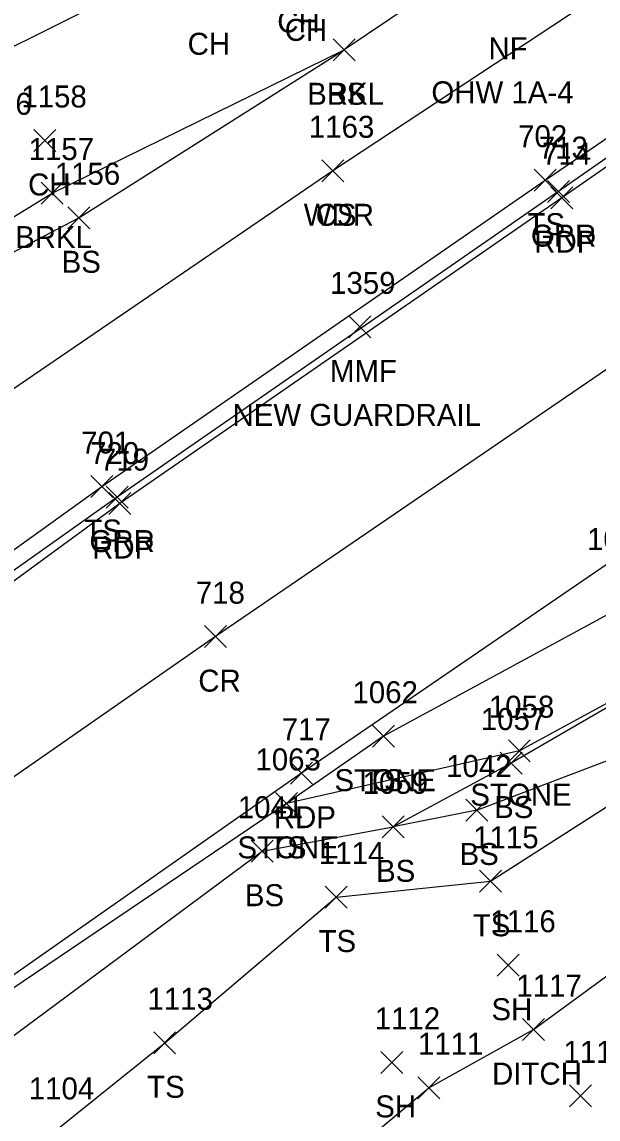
# Model space of a CAD drawing. Extents: x 1528286 to 1556263, y 492387 to 508952.
# Drawn here: x 1528810.2 to 1528862.6, y 492861.6 to 492961.3 of the extents above; entities that cross this region are included whole.
import ezdxf

# ---------------------------------------------------------------- set-up
doc = ezdxf.new("R2010")
doc.units = 0
for name, color, linetype in [('D_A', 7, 'Continuous'), ('D_I', 7, 'Continuous'), ('D_TIC', 7, 'Continuous'), ('DD', 7, 'Continuous'), ('L_A', 7, 'Continuous'), ('L_C', 7, 'Continuous'), ('L_I', 7, 'Continuous'), ('L_TIC', 7, 'Continuous'), ('LASF', 7, 'Continuous'), ('LAWA', 7, 'Continuous'), ('LAWE', 7, 'Continuous'), ('LELB', 7, 'Continuous'), ('P_A', 7, 'Continuous'), ('P_I', 7, 'Continuous'), ('P_TIC', 7, 'Continuous'), ('PET', 7, 'Continuous'), ('PRC', 7, 'Continuous'), ('R_A', 7, 'Continuous'), ('R_I', 7, 'Continuous'), ('R_TIC', 7, 'Continuous'), ('RGR', 7, 'Continuous')]:
    doc.layers.add(name, color=color, linetype=linetype)

msp = doc.modelspace()

# ---------------------------------------------------------------- linework, layer by layer
at = {"layer": 'D_TIC'}
for points in [[(1528855.697, 492868.705), (1528857.697, 492870.705)], [(1528857.697, 492868.705), (1528855.697, 492870.705)], [(1528855.697, 492868.705), (1528857.697, 492870.705)], [(1528857.697, 492868.705), (1528855.697, 492870.705)], [(1528846.183, 492863.422), (1528848.183, 492865.422)], [(1528848.183, 492863.422), (1528846.183, 492865.422)], [(1528846.183, 492863.422), (1528848.183, 492865.422)], [(1528848.183, 492863.422), (1528846.183, 492865.422)]]:
    msp.add_lwpolyline(points, dxfattribs=at)
at = {"layer": 'DD'}
msp.add_lwpolyline([(1528821.309, 492845.775), (1528834.865, 492854.142), (1528847.183, 492864.422), (1528856.697, 492869.705), (1528876.113, 492883.9), (1528885.264, 492891.293)], dxfattribs=at)
msp.add_lwpolyline([(1528821.309, 492845.775), (1528834.865, 492854.142), (1528847.183, 492864.422), (1528856.697, 492869.705), (1528876.113, 492883.9), (1528885.264, 492891.293)], dxfattribs=at)
at = {"layer": 'L_TIC'}
for points in [[(1528838.473, 492957.791), (1528840.473, 492959.791)], [(1528840.473, 492957.791), (1528838.473, 492959.791)], [(1528838.473, 492957.791), (1528840.473, 492959.791)], [(1528840.473, 492957.791), (1528838.473, 492959.791)], [(1528838.473, 492957.791), (1528840.473, 492959.791)], [(1528840.473, 492957.791), (1528838.473, 492959.791)], [(1528838.473, 492957.791), (1528840.473, 492959.791)], [(1528840.473, 492957.791), (1528838.473, 492959.791)], [(1528811.255, 492949.545), (1528813.255, 492951.545)], [(1528813.255, 492949.545), (1528811.255, 492951.545)], [(1528811.255, 492949.545), (1528813.255, 492951.545)], [(1528813.255, 492949.545), (1528811.255, 492951.545)], [(1528837.449, 492946.788), (1528839.449, 492948.788)], [(1528839.449, 492946.788), (1528837.449, 492948.788)], [(1528837.449, 492946.788), (1528839.449, 492948.788)], [(1528839.449, 492946.788), (1528837.449, 492948.788)], [(1528837.449, 492946.788), (1528839.449, 492948.788)], [(1528839.449, 492946.788), (1528837.449, 492948.788)], [(1528837.449, 492946.788), (1528839.449, 492948.788)], [(1528839.449, 492946.788), (1528837.449, 492948.788)], [(1528856.746, 492945.937), (1528858.746, 492947.937)], [(1528858.746, 492945.937), (1528856.746, 492947.937)], [(1528856.746, 492945.937), (1528858.746, 492947.937)], [(1528858.746, 492945.937), (1528856.746, 492947.937)], [(1528811.92, 492944.763), (1528813.92, 492946.763)], [(1528813.92, 492944.763), (1528811.92, 492946.763)], [(1528811.92, 492944.763), (1528813.92, 492946.763)], [(1528813.92, 492944.763), (1528811.92, 492946.763)], [(1528814.352, 492942.517), (1528816.352, 492944.517)], [(1528816.352, 492942.517), (1528814.352, 492944.517)], [(1528814.352, 492942.517), (1528816.352, 492944.517)], [(1528816.352, 492942.517), (1528814.352, 492944.517)], [(1528839.906, 492932.599), (1528841.906, 492934.599)], [(1528841.906, 492932.599), (1528839.906, 492934.599)], [(1528839.906, 492932.599), (1528841.906, 492934.599)], [(1528841.906, 492932.599), (1528839.906, 492934.599)], [(1528816.445, 492918.082), (1528818.445, 492920.082)], [(1528818.445, 492918.082), (1528816.445, 492920.082)], [(1528816.445, 492918.082), (1528818.445, 492920.082)], [(1528818.445, 492918.082), (1528816.445, 492920.082)], [(1528842.058, 492895.384), (1528844.058, 492897.384)], [(1528844.058, 492895.384), (1528842.058, 492897.384)], [(1528842.058, 492895.384), (1528844.058, 492897.384)], [(1528844.058, 492895.384), (1528842.058, 492897.384)], [(1528842.058, 492895.384), (1528844.058, 492897.384)], [(1528844.058, 492895.384), (1528842.058, 492897.384)], [(1528842.058, 492895.384), (1528844.058, 492897.384)], [(1528844.058, 492895.384), (1528842.058, 492897.384)], [(1528854.412, 492894.062), (1528856.412, 492896.062)], [(1528856.412, 492894.062), (1528854.412, 492896.062)], [(1528854.412, 492894.062), (1528856.412, 492896.062)], [(1528856.412, 492894.062), (1528854.412, 492896.062)], [(1528853.678, 492892.942), (1528855.678, 492894.942)], [(1528855.678, 492892.942), (1528853.678, 492894.942)], [(1528853.678, 492892.942), (1528855.678, 492894.942)], [(1528855.678, 492892.942), (1528853.678, 492894.942)], [(1528833.233, 492889.275), (1528835.233, 492891.275)], [(1528835.233, 492889.275), (1528833.233, 492891.275)], [(1528833.233, 492889.275), (1528835.233, 492891.275)], [(1528835.233, 492889.275), (1528833.233, 492891.275)], [(1528833.233, 492889.275), (1528835.233, 492891.275)], [(1528835.233, 492889.275), (1528833.233, 492891.275)], [(1528833.233, 492889.275), (1528835.233, 492891.275)], [(1528835.233, 492889.275), (1528833.233, 492891.275)], [(1528833.233, 492889.275), (1528835.233, 492891.275)], [(1528835.233, 492889.275), (1528833.233, 492891.275)], [(1528833.233, 492889.275), (1528835.233, 492891.275)], [(1528835.233, 492889.275), (1528833.233, 492891.275)], [(1528850.535, 492888.673), (1528852.535, 492890.673)], [(1528852.535, 492888.673), (1528850.535, 492890.673)], [(1528850.535, 492888.673), (1528852.535, 492890.673)], [(1528852.535, 492888.673), (1528850.535, 492890.673)], [(1528842.943, 492887.142), (1528844.943, 492889.142)], [(1528844.943, 492887.142), (1528842.943, 492889.142)], [(1528842.943, 492887.142), (1528844.943, 492889.142)], [(1528844.943, 492887.142), (1528842.943, 492889.142)], [(1528831.015, 492884.927), (1528833.015, 492886.927)], [(1528833.015, 492884.927), (1528831.015, 492886.927)], [(1528831.015, 492884.927), (1528833.015, 492886.927)], [(1528833.015, 492884.927), (1528831.015, 492886.927)], [(1528851.776, 492882.19), (1528853.776, 492884.19)], [(1528853.776, 492882.19), (1528851.776, 492884.19)], [(1528851.776, 492882.19), (1528853.776, 492884.19)], [(1528853.776, 492882.19), (1528851.776, 492884.19)], [(1528837.745, 492880.757), (1528839.745, 492882.757)], [(1528839.745, 492880.757), (1528837.745, 492882.757)], [(1528837.745, 492880.757), (1528839.745, 492882.757)], [(1528839.745, 492880.757), (1528837.745, 492882.757)], [(1528853.388, 492874.56), (1528855.388, 492876.56)], [(1528855.388, 492874.56), (1528853.388, 492876.56)], [(1528853.388, 492874.56), (1528855.388, 492876.56)], [(1528855.388, 492874.56), (1528853.388, 492876.56)], [(1528822.162, 492867.505), (1528824.162, 492869.505)], [(1528824.162, 492867.505), (1528822.162, 492869.505)], [(1528822.162, 492867.505), (1528824.162, 492869.505)], [(1528824.162, 492867.505), (1528822.162, 492869.505)], [(1528842.818, 492865.724), (1528844.818, 492867.724)], [(1528844.818, 492865.724), (1528842.818, 492867.724)], [(1528842.818, 492865.724), (1528844.818, 492867.724)], [(1528844.818, 492865.724), (1528842.818, 492867.724)], [(1528859.987, 492862.683), (1528861.987, 492864.683)], [(1528861.987, 492862.683), (1528859.987, 492864.683)], [(1528859.987, 492862.683), (1528861.987, 492864.683)], [(1528861.987, 492862.683), (1528859.987, 492864.683)]]:
    msp.add_lwpolyline(points, dxfattribs=at)
at = {"layer": 'LASF'}
for points in [[(1528892.931, 492919.077), (1528869.957, 492910.976), (1528843.058, 492896.384), (1528834.233, 492890.275)], [(1528892.931, 492919.077), (1528869.957, 492910.976), (1528843.058, 492896.384), (1528834.233, 492890.275)], [(1528890.826, 492909.115), (1528874.507, 492905.431), (1528855.412, 492895.062), (1528834.233, 492890.275)], [(1528890.826, 492909.115), (1528874.507, 492905.431), (1528855.412, 492895.062), (1528834.233, 492890.275)]]:
    msp.add_lwpolyline(points, dxfattribs=at)
at = {"layer": 'LAWA'}
msp.add_lwpolyline([(1528932.821, 493004.859), (1528877.302, 492973.439), (1528838.449, 492947.788), (1528805.62, 492925.402), (1528761.436, 492893.561), (1528731.583, 492876.413)], dxfattribs=at)
msp.add_lwpolyline([(1528932.821, 493004.859), (1528877.302, 492973.439), (1528838.449, 492947.788), (1528805.62, 492925.402), (1528761.436, 492893.561), (1528731.583, 492876.413)], dxfattribs=at)
at = {"layer": 'LAWE'}
for points in [[(1528718.656, 492995.484), (1528788.188, 492988.485), (1528851.648, 492980.148), (1528805.688, 492957.255), (1528774.988, 492939.585), (1528746.812, 492927.03)], [(1528718.656, 492995.484), (1528788.188, 492988.485), (1528851.648, 492980.148), (1528805.688, 492957.255), (1528774.988, 492939.585), (1528746.812, 492927.03)], [(1528860.159, 492972.685), (1528839.473, 492958.791)], [(1528860.159, 492972.685), (1528839.473, 492958.791)], [(1528699.698, 492858.914), (1528705.195, 492868.423), (1528711.604, 492880.328), (1528733.006, 492898.336), (1528756.206, 492910.282), (1528789.072, 492931.124), (1528812.92, 492945.763), (1528839.473, 492958.791)], [(1528699.698, 492858.914), (1528705.195, 492868.423), (1528711.604, 492880.328), (1528733.006, 492898.336), (1528756.206, 492910.282), (1528789.072, 492931.124), (1528812.92, 492945.763), (1528839.473, 492958.791)]]:
    msp.add_lwpolyline(points, dxfattribs=at)
at = {"layer": 'LELB'}
for points in [[(1528932.821, 493004.859), (1528877.302, 492973.439), (1528838.449, 492947.788), (1528805.62, 492925.402)], [(1528932.821, 493004.859), (1528877.302, 492973.439), (1528838.449, 492947.788), (1528805.62, 492925.402)], [(1528511.531, 492702.846), (1528534.14, 492721.314), (1528572.642, 492751.164), (1528586.729, 492763.586), (1528600.497, 492766.346), (1528613.458, 492775.516), (1528652.2, 492802.526), (1528688.619, 492828.262), (1528710.289, 492843.118), (1528742.907, 492866.471), (1528778.713, 492891.266), (1528817.445, 492919.082), (1528857.746, 492946.937), (1528897.372, 492973.983), (1528940.286, 493003.739)], [(1528511.531, 492702.846), (1528534.14, 492721.314), (1528572.642, 492751.164), (1528586.729, 492763.586), (1528600.497, 492766.346), (1528613.458, 492775.516), (1528652.2, 492802.526), (1528688.619, 492828.262), (1528710.289, 492843.118), (1528742.907, 492866.471), (1528778.713, 492891.266), (1528817.445, 492919.082), (1528857.746, 492946.937), (1528897.372, 492973.983), (1528940.286, 493003.739)], [(1528716.329, 492882.991), (1528739.424, 492897.091), (1528757.723, 492908.665), (1528787.402, 492928.88), (1528815.352, 492943.517), (1528839.473, 492958.791)], [(1528716.329, 492882.991), (1528739.424, 492897.091), (1528757.723, 492908.665), (1528787.402, 492928.88), (1528815.352, 492943.517), (1528839.473, 492958.791)], [(1528946.969, 492932.586), (1528919.959, 492926.163), (1528896.398, 492920.638), (1528892.931, 492919.077), (1528869.957, 492910.976), (1528843.058, 492896.384), (1528834.233, 492890.275), (1528806.992, 492871.856), (1528782.492, 492854.983), (1528750.989, 492833.046), (1528710.78, 492805.361), (1528694.188, 492792.448), (1528682.217, 492773.575), (1528672.784, 492775.788)], [(1528946.969, 492932.586), (1528919.959, 492926.163), (1528896.398, 492920.638), (1528892.931, 492919.077), (1528869.957, 492910.976), (1528843.058, 492896.384), (1528834.233, 492890.275), (1528806.992, 492871.856), (1528782.492, 492854.983), (1528750.989, 492833.046), (1528710.78, 492805.361), (1528694.188, 492792.448), (1528682.217, 492773.575), (1528672.784, 492775.788)], [(1528950.166, 492932.924), (1528948.057, 492927.676), (1528921.827, 492922.221), (1528901.569, 492912.915), (1528890.826, 492909.115), (1528874.507, 492905.431), (1528854.678, 492893.942), (1528843.943, 492888.142)], [(1528950.166, 492932.924), (1528948.057, 492927.676), (1528921.827, 492922.221), (1528901.569, 492912.915), (1528890.826, 492909.115), (1528874.507, 492905.431), (1528854.678, 492893.942), (1528843.943, 492888.142)], [(1528851.535, 492889.673), (1528882.303, 492901.371), (1528923.156, 492918.133), (1528948.593, 492924.145), (1528953.496, 492933.309)], [(1528851.535, 492889.673), (1528882.303, 492901.371), (1528923.156, 492918.133), (1528948.593, 492924.145), (1528953.496, 492933.309)], [(1528771.365, 492833.538), (1528790.046, 492845.146), (1528813.011, 492860.356), (1528823.162, 492868.505), (1528838.745, 492881.757), (1528852.776, 492883.19), (1528874.04, 492896.82), (1528872.111, 492886.309)], [(1528771.365, 492833.538), (1528790.046, 492845.146), (1528813.011, 492860.356), (1528823.162, 492868.505), (1528838.745, 492881.757), (1528852.776, 492883.19), (1528874.04, 492896.82), (1528872.111, 492886.309)], [(1528851.535, 492889.673), (1528843.943, 492888.142)], [(1528851.535, 492889.673), (1528843.943, 492888.142)], [(1528832.015, 492885.927), (1528843.943, 492888.142)], [(1528832.015, 492885.927), (1528843.943, 492888.142)], [(1528675.196, 492746.898), (1528689.3, 492770.432), (1528699.745, 492780.853), (1528706.225, 492795.334), (1528738.423, 492819.149), (1528757.61, 492832.596), (1528783.379, 492849.877), (1528832.015, 492885.927)], [(1528675.196, 492746.898), (1528689.3, 492770.432), (1528699.745, 492780.853), (1528706.225, 492795.334), (1528738.423, 492819.149), (1528757.61, 492832.596), (1528783.379, 492849.877), (1528832.015, 492885.927)]]:
    msp.add_lwpolyline(points, dxfattribs=at)
at = {"layer": 'P_TIC'}
for points in [[(1528858.279, 492944.341), (1528860.279, 492946.341)], [(1528860.279, 492944.341), (1528858.279, 492946.341)], [(1528858.279, 492944.341), (1528860.279, 492946.341)], [(1528860.279, 492944.341), (1528858.279, 492946.341)], [(1528818.079, 492916.533), (1528820.079, 492918.533)], [(1528820.079, 492916.533), (1528818.079, 492918.533)], [(1528818.079, 492916.533), (1528820.079, 492918.533)], [(1528820.079, 492916.533), (1528818.079, 492918.533)], [(1528826.787, 492904.434), (1528828.787, 492906.434)], [(1528828.787, 492904.434), (1528826.787, 492906.434)], [(1528826.787, 492904.434), (1528828.787, 492906.434)], [(1528828.787, 492904.434), (1528826.787, 492906.434)], [(1528834.6, 492892.02), (1528836.6, 492894.02)], [(1528836.6, 492892.02), (1528834.6, 492894.02)], [(1528834.6, 492892.02), (1528836.6, 492894.02)], [(1528836.6, 492892.02), (1528834.6, 492894.02)]]:
    msp.add_lwpolyline(points, dxfattribs=at)
at = {"layer": 'PET'}
for points in [[(1528941.998, 493002.12), (1528898.48, 492972.509), (1528859.279, 492945.341), (1528819.079, 492917.533), (1528787.553, 492894.483), (1528780.465, 492889.936), (1528744.229, 492865.118), (1528711.173, 492841.816), (1528689.558, 492826.658), (1528653.332, 492801.515)], [(1528941.998, 493002.12), (1528898.48, 492972.509), (1528859.279, 492945.341), (1528819.079, 492917.533), (1528787.553, 492894.483), (1528780.465, 492889.936), (1528744.229, 492865.118), (1528711.173, 492841.816), (1528689.558, 492826.658), (1528653.332, 492801.515)], [(1528958.712, 492978.015), (1528915.24, 492947.631), (1528876.045, 492920.659), (1528835.6, 492893.02)], [(1528958.712, 492978.015), (1528915.24, 492947.631), (1528876.045, 492920.659), (1528835.6, 492893.02)], [(1528835.6, 492893.02), (1528803.826, 492870.766)], [(1528835.6, 492893.02), (1528803.826, 492870.766)]]:
    msp.add_lwpolyline(points, dxfattribs=at)
at = {"layer": 'PRC'}
for points in [[(1528950.02, 492989.767), (1528907.211, 492960.288), (1528867.742, 492932.713), (1528827.787, 492905.434)], [(1528950.02, 492989.767), (1528907.211, 492960.288), (1528867.742, 492932.713), (1528827.787, 492905.434)], [(1528827.787, 492905.434), (1528795.629, 492883.094)], [(1528827.787, 492905.434), (1528795.629, 492883.094)]]:
    msp.add_lwpolyline(points, dxfattribs=at)
at = {"layer": 'R_TIC'}
for points in [[(1528857.975, 492944.897), (1528859.975, 492946.897)], [(1528859.975, 492944.897), (1528857.975, 492946.897)], [(1528857.975, 492944.897), (1528859.975, 492946.897)], [(1528859.975, 492944.897), (1528857.975, 492946.897)], [(1528817.829, 492917.12), (1528819.829, 492919.12)], [(1528819.829, 492917.12), (1528817.829, 492919.12)], [(1528817.829, 492917.12), (1528819.829, 492919.12)], [(1528819.829, 492917.12), (1528817.829, 492919.12)]]:
    msp.add_lwpolyline(points, dxfattribs=at)
at = {"layer": 'RGR'}
msp.add_lwpolyline([(1528941.405, 493002.785), (1528898.116, 492973.218), (1528858.975, 492945.897), (1528818.829, 492918.12), (1528780.054, 492890.637), (1528744.146, 492865.314), (1528711.237, 492842.066), (1528689.599, 492826.87), (1528653.301, 492801.623)], dxfattribs=at)
msp.add_lwpolyline([(1528941.405, 493002.785), (1528898.116, 492973.218), (1528858.975, 492945.897), (1528818.829, 492918.12), (1528780.054, 492890.637), (1528744.146, 492865.314), (1528711.237, 492842.066), (1528689.599, 492826.87), (1528653.301, 492801.623)], dxfattribs=at)

# ---------------------------------------------------------------- texts
at = {"layer": 'D_A'}
msp.add_text('DITCH', height=2, dxfattribs=at).set_placement((1528852.933, 492864.705))
msp.add_text('DITCH', height=2, dxfattribs=at).set_placement((1528852.933, 492864.705))
at = {"layer": 'D_I'}
for s, p in [('1117', (1528855.138, 492872.705)), ('1117', (1528855.138, 492872.705)), ('1111', (1528846.191, 492867.422)), ('1111', (1528846.191, 492867.422))]:
    msp.add_text(s, height=2, dxfattribs=at).set_placement(p)
at = {"layer": 'L_A'}
for s, p in [('CH', (1528833.399, 492960.372)), ('CH', (1528833.399, 492960.372)), ('CH', (1528834.077, 492959.601)), ('CH', (1528834.077, 492959.601)), ('CH', (1528825.249, 492958.336)), ('CH', (1528825.249, 492958.336)), ('NF', (1528852.604, 492957.924)), ('NF', (1528852.604, 492957.924)), ('BRKL', (1528836.119, 492953.791)), ('BRKL', (1528836.119, 492953.791)), ('BS', (1528837.914, 492953.791)), ('BS', (1528837.914, 492953.791)), ('CH', (1528810.743, 492945.545)), ('CH', (1528810.743, 492945.545)), ('WDR', (1528835.811, 492942.788)), ('WDR', (1528835.811, 492942.788)), ('CS', (1528836.89, 492942.788)), ('CS', (1528836.89, 492942.788)), ('TS', (1528856.155, 492941.937)), ('TS', (1528856.155, 492941.937)), ('BRKL', (1528809.566, 492940.763)), ('BRKL', (1528809.566, 492940.763)), ('BS', (1528813.793, 492938.517)), ('BS', (1528813.793, 492938.517)), ('MMF', (1528838.189, 492928.599)), ('MMF', (1528838.189, 492928.599)), ('TS', (1528815.855, 492914.082)), ('TS', (1528815.855, 492914.082)), ('STONE', (1528838.601, 492891.384)), ('STONE', (1528838.601, 492891.384)), ('TS', (1528841.467, 492891.384)), ('TS', (1528841.467, 492891.384)), ('STONE', (1528850.955, 492890.062)), ('STONE', (1528850.955, 492890.062)), ('BS', (1528853.119, 492888.942)), ('BS', (1528853.119, 492888.942)), ('STONE', (1528829.777, 492885.275)), ('STONE', (1528829.777, 492885.275)), ('STONE', (1528829.777, 492885.275)), ('STONE', (1528829.777, 492885.275)), ('TS', (1528832.643, 492885.275)), ('TS', (1528832.643, 492885.275)), ('BS', (1528849.976, 492884.673)), ('BS', (1528849.976, 492884.673)), ('BS', (1528842.384, 492883.142)), ('BS', (1528842.384, 492883.142)), ('BS', (1528830.456, 492880.927)), ('BS', (1528830.456, 492880.927)), ('TS', (1528851.185, 492878.19)), ('TS', (1528851.185, 492878.19)), ('TS', (1528837.154, 492876.757)), ('TS', (1528837.154, 492876.757)), ('SH', (1528852.876, 492870.56)), ('SH', (1528852.876, 492870.56)), ('TS', (1528821.571, 492863.505)), ('TS', (1528821.571, 492863.505)), ('SH', (1528842.307, 492861.724)), ('SH', (1528842.307, 492861.724))]:
    msp.add_text(s, height=2, dxfattribs=at).set_placement(p)
at = {"layer": 'L_C'}
for s, p in [('OHW 1A-4', (1528847.415, 492953.924)), ('OHW 1A-4', (1528847.415, 492953.924)), ('NEW GUARDRAIL', (1528829.331, 492924.599)), ('NEW GUARDRAIL', (1528829.331, 492924.599))]:
    msp.add_text(s, height=2, dxfattribs=at).set_placement(p)
at = {"layer": 'L_I'}
for s, p in [('1158', (1528810.129, 492953.545)), ('1158', (1528810.129, 492953.545)), ('1356', (1528805.123, 492952.886)), ('1356', (1528805.123, 492952.886)), ('1163', (1528836.276, 492950.788)), ('1163', (1528836.276, 492950.788)), ('1163', (1528836.276, 492950.788)), ('1163', (1528836.276, 492950.788)), ('702', (1528855.305, 492949.937)), ('702', (1528855.305, 492949.937)), ('1157', (1528810.794, 492948.763)), ('1157', (1528810.794, 492948.763)), ('1156', (1528813.17, 492946.517)), ('1156', (1528813.17, 492946.517)), ('1359', (1528838.205, 492936.599)), ('1359', (1528838.205, 492936.599)), ('701', (1528815.571, 492922.082)), ('701', (1528815.571, 492922.082)), ('1064', (1528861.57, 492913.31)), ('1064', (1528861.57, 492913.31)), ('1062', (1528840.239, 492899.384)), ('1062', (1528840.239, 492899.384)), ('1062', (1528840.239, 492899.384)), ('1062', (1528840.239, 492899.384)), ('1058', (1528852.64, 492898.062)), ('1058', (1528852.64, 492898.062)), ('1057', (1528851.906, 492896.942)), ('1057', (1528851.906, 492896.942)), ('1063', (1528831.415, 492893.275)), ('1063', (1528831.415, 492893.275)), ('1063', (1528831.415, 492893.275)), ('1063', (1528831.415, 492893.275)), ('1063', (1528831.415, 492893.275)), ('1063', (1528831.415, 492893.275)), ('1042', (1528848.764, 492892.673)), ('1042', (1528848.764, 492892.673)), ('1059', (1528841.164, 492891.142)), ('1059', (1528841.164, 492891.142)), ('1041', (1528829.81, 492888.927)), ('1041', (1528829.81, 492888.927)), ('1115', (1528851.217, 492886.19)), ('1115', (1528851.217, 492886.19)), ('1114', (1528837.186, 492884.757)), ('1114', (1528837.186, 492884.757)), ('1116', (1528852.774, 492878.56)), ('1116', (1528852.774, 492878.56)), ('1113', (1528821.603, 492871.505)), ('1113', (1528821.603, 492871.505)), ('1112', (1528842.259, 492869.724)), ('1112', (1528842.259, 492869.724)), ('1118', (1528859.427, 492866.683)), ('1118', (1528859.427, 492866.683)), ('1104', (1528810.806, 492863.356)), ('1104', (1528810.806, 492863.356))]:
    msp.add_text(s, height=2, dxfattribs=at).set_placement(p)
at = {"layer": 'P_A'}
for s, p in [('RDP', (1528856.767, 492940.341)), ('RDP', (1528856.767, 492940.341)), ('RDP', (1528816.567, 492912.533)), ('RDP', (1528816.567, 492912.533)), ('CR', (1528826.22, 492900.434)), ('CR', (1528826.22, 492900.434)), ('RDP', (1528833.088, 492888.02)), ('RDP', (1528833.088, 492888.02))]:
    msp.add_text(s, height=2, dxfattribs=at).set_placement(p)
at = {"layer": 'P_I'}
for s, p in [('714', (1528857.483, 492948.341)), ('714', (1528857.483, 492948.341)), ('719', (1528817.276, 492920.533)), ('719', (1528817.276, 492920.533)), ('718', (1528825.992, 492908.434)), ('718', (1528825.992, 492908.434)), ('717', (1528833.805, 492896.02)), ('717', (1528833.805, 492896.02))]:
    msp.add_text(s, height=2, dxfattribs=at).set_placement(p)
at = {"layer": 'R_A'}
for p in [(1528856.463, 492940.897), (1528856.463, 492940.897), (1528816.317, 492913.12), (1528816.317, 492913.12)]:
    msp.add_text('GRR', height=2, dxfattribs=at).set_placement(p)
at = {"layer": 'R_I'}
for s, p in [('713', (1528857.18, 492948.897)), ('713', (1528857.18, 492948.897)), ('720', (1528816.38, 492921.12)), ('720', (1528816.38, 492921.12))]:
    msp.add_text(s, height=2, dxfattribs=at).set_placement(p)

doc.saveas('drawing.dxf')
